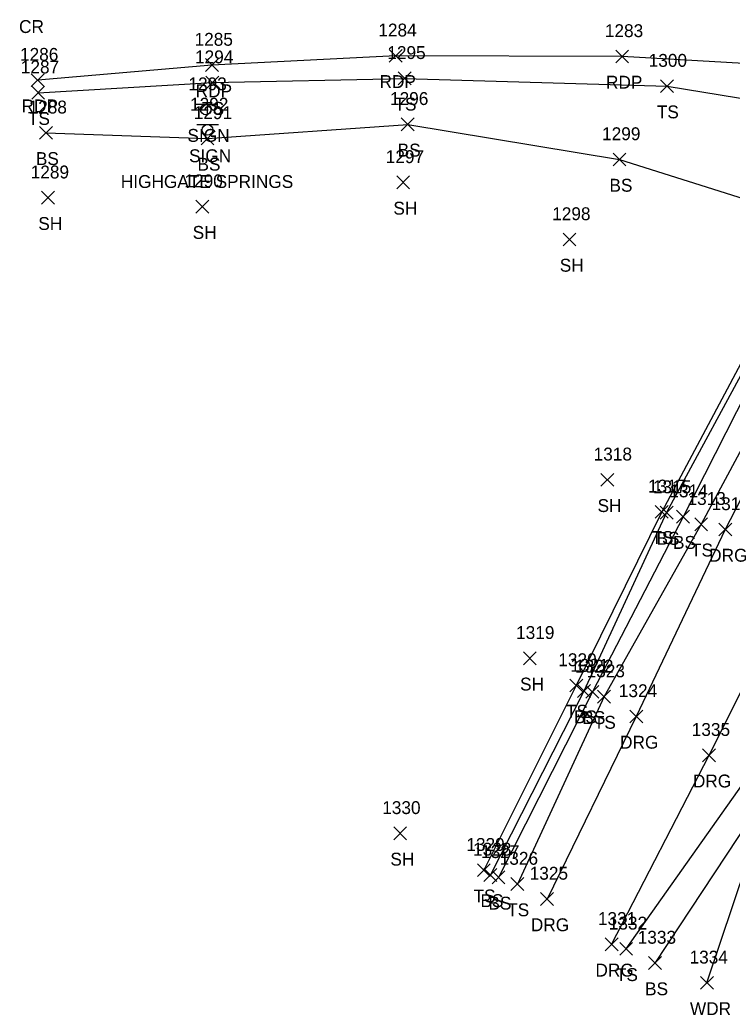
# Model space of a CAD drawing. Extents: x 1485624 to 1495982, y 886445 to 890805.
# Drawn here: x 1495487.2 to 1495597.7, y 890450.3 to 890604.8 of the extents above; entities that cross this region are included whole.
import ezdxf

# ---------------------------------------------------------------- set-up
doc = ezdxf.new("R2010")
doc.units = 0
for name, color, linetype in [('L_A', 7, 'Continuous'), ('L_I', 7, 'Continuous'), ('L_TIC', 7, 'Continuous'), ('LAWA', 7, 'Continuous'), ('LELB', 7, 'Continuous'), ('P_A', 7, 'Continuous'), ('P_I', 7, 'Continuous'), ('P_TIC', 7, 'Continuous'), ('PET', 7, 'Continuous'), ('R_A', 7, 'Continuous'), ('R_I', 7, 'Continuous'), ('R_TIC', 7, 'Continuous'), ('RDG', 7, 'Continuous'), ('S_A', 7, 'Continuous'), ('S_C', 7, 'Continuous'), ('S_I', 7, 'Continuous'), ('SSGN', 7, 'Continuous')]:
    doc.layers.add(name, color=color, linetype=linetype)

msp = doc.modelspace()

# ---------------------------------------------------------------- linework, layer by layer
at = {"layer": 'L_TIC'}
for points in [[(1495516.04, 890594.05), (1495518.04, 890596.05)], [(1495518.04, 890594.05), (1495516.04, 890596.05)], [(1495545.88, 890594.72), (1495547.88, 890596.72)], [(1495547.88, 890594.72), (1495545.88, 890596.72)], [(1495489.02, 890592.49), (1495491.02, 890594.49)], [(1495491.02, 890592.49), (1495489.02, 890594.49)], [(1495586.58, 890593.51), (1495588.58, 890595.51)], [(1495588.58, 890593.51), (1495586.58, 890595.51)], [(1495546.35, 890587.58), (1495548.35, 890589.58)], [(1495548.35, 890587.58), (1495546.35, 890589.58)], [(1495490.22, 890586.26), (1495492.22, 890588.26)], [(1495492.22, 890586.26), (1495490.22, 890588.26)], [(1495515.29, 890585.39), (1495517.29, 890587.39)], [(1495517.29, 890585.39), (1495515.29, 890587.39)], [(1495579.2, 890582.12), (1495581.2, 890584.12)], [(1495581.2, 890582.12), (1495579.2, 890584.12)], [(1495545.64, 890578.56), (1495547.64, 890580.56)], [(1495547.64, 890578.56), (1495545.64, 890580.56)], [(1495490.56, 890576.18), (1495492.56, 890578.18)], [(1495492.56, 890576.18), (1495490.56, 890578.18)], [(1495514.5, 890574.8), (1495516.5, 890576.8)], [(1495516.5, 890574.8), (1495514.5, 890576.8)], [(1495571.45, 890569.7), (1495573.45, 890571.7)], [(1495573.45, 890569.7), (1495571.45, 890571.7)], [(1495577.32, 890532.39), (1495579.32, 890534.39)], [(1495579.32, 890532.39), (1495577.32, 890534.39)], [(1495585.75, 890527.42), (1495587.75, 890529.42)], [(1495587.75, 890527.42), (1495585.75, 890529.42)], [(1495586.51, 890527.3), (1495588.51, 890529.3)], [(1495588.51, 890527.3), (1495586.51, 890529.3)], [(1495589.06, 890526.67), (1495591.06, 890528.67)], [(1495591.06, 890526.67), (1495589.06, 890528.67)], [(1495591.88, 890525.49), (1495593.88, 890527.49)], [(1495593.88, 890525.49), (1495591.88, 890527.49)], [(1495565.29, 890504.68), (1495567.29, 890506.68)], [(1495567.29, 890504.68), (1495565.29, 890506.68)], [(1495572.49, 890500.46), (1495574.49, 890502.46)], [(1495574.49, 890500.46), (1495572.49, 890502.46)], [(1495573.69, 890499.59), (1495575.69, 890501.59)], [(1495575.69, 890499.59), (1495573.69, 890501.59)], [(1495575, 890499.47), (1495577, 890501.47)], [(1495577, 890499.47), (1495575, 890501.47)], [(1495576.8, 890498.74), (1495578.8, 890500.74)], [(1495578.8, 890498.74), (1495576.8, 890500.74)], [(1495545.17, 890477.5), (1495547.17, 890479.5)], [(1495547.17, 890477.5), (1495545.17, 890479.5)], [(1495558.15, 890471.78), (1495560.15, 890473.78)], [(1495560.15, 890471.78), (1495558.15, 890473.78)], [(1495559.18, 890471.05), (1495561.18, 890473.05)], [(1495561.18, 890471.05), (1495559.18, 890473.05)], [(1495560.43, 890470.67), (1495562.43, 890472.67)], [(1495562.43, 890470.67), (1495560.43, 890472.67)], [(1495563.37, 890469.63), (1495565.37, 890471.63)], [(1495565.37, 890469.63), (1495563.37, 890471.63)], [(1495580.23, 890459.57), (1495582.23, 890461.57)], [(1495582.23, 890459.57), (1495580.23, 890461.57)], [(1495584.72, 890457.37), (1495586.72, 890459.37)], [(1495586.72, 890457.37), (1495584.72, 890459.37)], [(1495592.77, 890454.29), (1495594.77, 890456.29)], [(1495594.77, 890454.29), (1495592.77, 890456.29)]]:
    msp.add_lwpolyline(points, dxfattribs=at)
at = {"layer": 'LAWA'}
msp.add_lwpolyline([(1495593.77, 890455.29), (1495604.16, 890486.25), (1495624.56, 890513.67), (1495629.05, 890516.16), (1495630.21, 890519.39)], dxfattribs=at)
at = {"layer": 'LELB'}
for points in [[(1495490.02, 890593.49), (1495517.04, 890595.05), (1495546.88, 890595.72), (1495587.58, 890594.51), (1495606.9, 890591.34), (1495613.07, 890582.71), (1495615.55, 890572.18), (1495610, 890558.37), (1495592.88, 890526.49), (1495577.8, 890499.74), (1495564.37, 890470.63)], [(1495491.22, 890587.26), (1495516.29, 890586.39), (1495547.35, 890588.58), (1495580.2, 890583.12), (1495612.18, 890573.05), (1495607.91, 890559.78), (1495603.33, 890553.72), (1495590.06, 890527.67), (1495576, 890500.47), (1495561.43, 890471.67)], [(1495606.23, 890560.58), (1495601.14, 890555.41), (1495586.75, 890528.42), (1495573.49, 890501.46), (1495559.15, 890472.78)], [(1495606.23, 890560.58), (1495601.73, 890554.61), (1495587.51, 890528.3), (1495574.69, 890500.59), (1495560.18, 890472.05)], [(1495581.23, 890460.57), (1495600.88, 890488.37), (1495619.54, 890516.71)], [(1495585.72, 890458.37), (1495604.16, 890486.25), (1495622.82, 890500.59)]]:
    msp.add_lwpolyline(points, dxfattribs=at)
at = {"layer": 'P_TIC'}
for points in [[(1495544.48, 890598.22), (1495546.48, 890600.22)], [(1495546.48, 890598.22), (1495544.48, 890600.22)], [(1495579.62, 890598.12), (1495581.62, 890600.12)], [(1495581.62, 890598.12), (1495579.62, 890600.12)], [(1495515.97, 890596.78), (1495517.97, 890598.78)], [(1495517.97, 890596.78), (1495515.97, 890598.78)], [(1495488.95, 890594.44), (1495490.95, 890596.44)], [(1495490.95, 890594.44), (1495488.95, 890596.44)]]:
    msp.add_lwpolyline(points, dxfattribs=at)
at = {"layer": 'PET'}
msp.add_lwpolyline([(1495603.97, 890597.77), (1495580.62, 890599.12), (1495545.48, 890599.22), (1495516.97, 890597.78), (1495489.95, 890595.44)], dxfattribs=at)
at = {"layer": 'R_TIC'}
for points in [[(1495595.62, 890524.68), (1495597.62, 890526.68)], [(1495597.62, 890524.68), (1495595.62, 890526.68)], [(1495581.8, 890495.65), (1495583.8, 890497.65)], [(1495583.8, 890495.65), (1495581.8, 890497.65)], [(1495593.1, 890489.63), (1495595.1, 890491.63)], [(1495595.1, 890489.63), (1495593.1, 890491.63)], [(1495567.96, 890467.31), (1495569.96, 890469.31)], [(1495569.96, 890467.31), (1495567.96, 890469.31)], [(1495577.98, 890460.27), (1495579.98, 890462.27)], [(1495579.98, 890460.27), (1495577.98, 890462.27)]]:
    msp.add_lwpolyline(points, dxfattribs=at)
at = {"layer": 'RDG'}
for points in [[(1495602.16, 890536.5), (1495596.62, 890525.68), (1495582.8, 890496.65), (1495568.96, 890468.31)], [(1495578.98, 890461.27), (1495594.1, 890490.63), (1495610.16, 890522.67)]]:
    msp.add_lwpolyline(points, dxfattribs=at)
at = {"layer": 'SSGN'}
for p, q in [((1495514.39, 890591.72), (1495517.73, 890591.72)), ((1495516.04, 890590.88), (1495516.04, 890590.88)), ((1495514.65, 890588.56), (1495517.98, 890588.56)), ((1495516.29, 890587.72), (1495516.29, 890587.72))]:
    msp.add_line(p, q, dxfattribs=at)
for centre in [(1495516.04, 890590.88), (1495516.29, 890587.72)]:
    msp.add_circle(centre, 0.833, dxfattribs=at)

# ---------------------------------------------------------------- texts
at = {"layer": 'L_A'}
for s, p in [('TS', (1495515.45, 890590.05)), ('TS', (1495545.29, 890590.72)), ('TS', (1495585.99, 890589.51)), ('TS', (1495488.43, 890588.49)), ('BS', (1495545.79, 890583.58)), ('BS', (1495489.66, 890582.26)), ('BS', (1495514.73, 890581.39)), ('BS', (1495578.64, 890578.12)), ('SH', (1495545.12, 890574.56)), ('SH', (1495490.04, 890572.18)), ('SH', (1495513.99, 890570.8)), ('SH', (1495570.94, 890565.7)), ('SH', (1495576.8, 890528.39)), ('TS', (1495585.16, 890523.42)), ('BS', (1495585.95, 890523.3)), ('BS', (1495588.5, 890522.67)), ('TS', (1495591.29, 890521.49)), ('SH', (1495564.78, 890500.68)), ('TS', (1495571.9, 890496.46)), ('BS', (1495573.13, 890495.59)), ('BS', (1495574.44, 890495.47)), ('TS', (1495576.21, 890494.74)), ('SH', (1495544.66, 890473.5)), ('TS', (1495557.56, 890467.78)), ('BS', (1495558.63, 890467.05)), ('BS', (1495559.87, 890466.67)), ('TS', (1495562.78, 890465.63)), ('TS', (1495579.64, 890455.57)), ('BS', (1495584.17, 890453.37)), ('WDR', (1495591.13, 890450.29))]:
    msp.add_text(s, height=2, dxfattribs=at).set_placement(p)
at = {"layer": 'L_I'}
for s, p in [('1295', (1495544.18, 890598.72)), ('1294', (1495514.35, 890598.05)), ('1300', (1495584.73, 890597.51)), ('1287', (1495487.33, 890596.49)), ('1296', (1495544.6, 890591.58)), ('1288', (1495488.53, 890590.26)), ('1291', (1495514.16, 890589.39)), ('1299', (1495577.5, 890586.12)), ('1297', (1495543.94, 890582.56)), ('1289', (1495488.86, 890580.18)), ('1290', (1495512.72, 890578.8)), ('1298', (1495569.76, 890573.7)), ('1318', (1495576.19, 890536.39)), ('1317', (1495584.63, 890531.42)), ('1315', (1495585.39, 890531.3)), ('1314', (1495587.94, 890530.67)), ('1313', (1495590.75, 890529.49)), ('1319', (1495564.16, 890508.68)), ('1320', (1495570.71, 890504.46)), ('1321', (1495572.56, 890503.59)), ('1322', (1495573.31, 890503.47)), ('1323', (1495575.1, 890502.74)), ('1330', (1495543.39, 890481.5)), ('1329', (1495556.45, 890475.78)), ('1328', (1495557.49, 890475.05)), ('1327', (1495558.73, 890474.67)), ('1326', (1495561.62, 890473.63)), ('1332', (1495578.54, 890463.57)), ('1333', (1495583.03, 890461.37)), ('1334', (1495591.07, 890458.29))]:
    msp.add_text(s, height=2, dxfattribs=at).set_placement(p)
at = {"layer": 'P_A'}
for s, p in [('CR', (1495487.05, 890602.76)), ('RDP', (1495542.97, 890594.22)), ('RDP', (1495578.11, 890594.12)), ('RDP', (1495514.46, 890592.78)), ('RDP', (1495487.44, 890590.44))]:
    msp.add_text(s, height=2, dxfattribs=at).set_placement(p)
at = {"layer": 'P_I'}
for s, p in [('1284', (1495542.79, 890602.22)), ('1283', (1495577.93, 890602.12)), ('1285', (1495514.28, 890600.78)), ('1286', (1495487.2, 890598.44))]:
    msp.add_text(s, height=2, dxfattribs=at).set_placement(p)
at = {"layer": 'R_A'}
for p in [(1495594.11, 890520.68), (1495580.29, 890491.65), (1495591.59, 890485.63), (1495566.45, 890463.31), (1495576.47, 890456.27)]:
    msp.add_text('DRG', height=2, dxfattribs=at).set_placement(p)
at = {"layer": 'R_I'}
for s, p in [('1312', (1495594.49, 890528.68)), ('1324', (1495580.1, 890499.65)), ('1335', (1495591.41, 890493.63)), ('1325', (1495566.27, 890471.31)), ('1331', (1495576.85, 890464.27))]:
    msp.add_text(s, height=2, dxfattribs=at).set_placement(p)
at = {"layer": 'S_A'}
for p in [(1495513.18, 890585.86), (1495513.43, 890582.7)]:
    msp.add_text('SIGN', height=2, dxfattribs=at).set_placement(p)
at = {"layer": 'S_C'}
msp.add_text('HIGHGATE SPRINGS', height=2, dxfattribs=at).set_placement((1495502.84, 890578.7))
at = {"layer": 'S_I'}
for s, p in [('1293', (1495513.33, 890593.86)), ('1292', (1495513.58, 890590.7))]:
    msp.add_text(s, height=2, dxfattribs=at).set_placement(p)

doc.saveas('drawing.dxf')
